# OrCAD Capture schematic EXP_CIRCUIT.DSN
size A
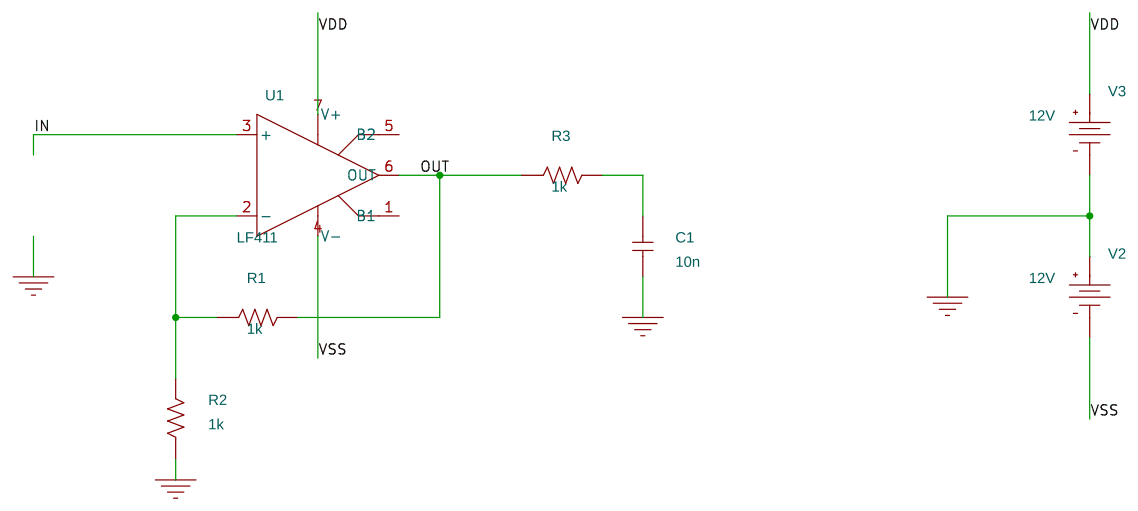
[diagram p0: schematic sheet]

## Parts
C1  10n  [cap196]
R1  1k  [AXRC05]
R2  1k  [AXRC05]
R3  1k  [AXRC05]
U1  LF411  [DIP1008W300L450]
V2  VDC
V3  VDC

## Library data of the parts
C1 = C
R1-R3 = R
U1 = LF411
V2 V3 = VDC: DC: 12V

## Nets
VDD: U1.7(V+) V3.0(+)
VSS: U1.4(V-) V2.1(-)
0: C1.1 R2.1 V2.0(+) V3.1(-)
IN: U1.3(+)
OUT: R1.2 R3.1 U1.6(OUT)
N00123: R1.1 R2.2 U1.2(-)
N05895: C1.2 R3.2

Not connected (* = marked no-connect by the designer): U1 1(B1) 5(B2)
